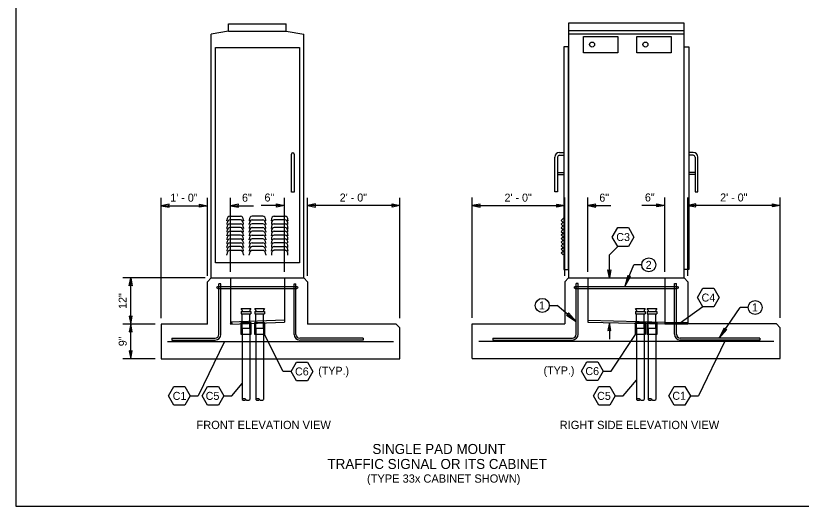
# Model space of a CAD drawing. Extents: x 99862 to 103151, y 100000 to 117076.
# Drawn here: x 99862 to 101432, y 109000 to 109981 of the extents above; entities that cross this region are included whole.
import ezdxf

# ---------------------------------------------------------------- set-up
doc = ezdxf.new("R2010")
doc.units = 0
for name, color, linetype in [('Default', 7, 'Continuous'), ('Level 1', 7, 'Continuous'), ('Level 11', 7, 'Continuous'), ('Level 15', 7, 'Continuous'), ('Level 20', 7, 'Continuous'), ('Level 40', 7, 'Continuous'), ('Level 6', 7, 'Continuous'), ('Level 60', 7, 'Continuous')]:
    doc.layers.add(name, color=color, linetype=linetype)

msp = doc.modelspace()

# ---------------------------------------------------------------- linework, layer by layer
at = {"layer": 'Default'}
for p, q in [((100266.2, 109439.1), (100424, 109439.1)), ((100266.2, 109435.2), (100424, 109435.2)), ((100268.2, 109343.5), (100268.2, 109444.9)), ((100272, 109444.9), (100268.2, 109444.9)), ((100272, 109343.5), (100272, 109444.9)), ((100418.2, 109343.5), (100418.2, 109444.9)), ((100418.2, 109444.9), (100422.1, 109444.9)), ((100422.1, 109343.5), (100422.1, 109444.9)), ((100980.4, 109439.3), (101184.3, 109439.3)), ((100980.4, 109435.4), (101184.3, 109435.4)), ((100982.3, 109343.7), (100982.3, 109445.1)), ((100986.2, 109445.1), (100982.3, 109445.1)), ((100986.2, 109343.7), (100986.2, 109445.1)), ((101178.5, 109343.7), (101178.5, 109445.1)), ((101178.5, 109445.1), (101182.4, 109445.1)), ((101182.4, 109343.7), (101182.4, 109445.1)), ((101159.3, 109367.1), (101205.5, 109367.1)), ((101159.3, 109364.3), (101205.5, 109364.3)), ((100173.9, 109335.9), (100173.9, 109332)), ((100173.9, 109335.9), (100260.5, 109335.9)), ((100173.9, 109332), (100260.5, 109332)), ((100556.2, 109335.9), (100429.8, 109335.9)), ((100556.2, 109332), (100429.8, 109332)), ((100556.2, 109335.9), (100556.2, 109332)), ((100815.4, 109336), (100815.4, 109332.2)), ((100815.4, 109336), (100974.6, 109336)), ((100815.4, 109332.2), (100974.6, 109332.2)), ((101349.3, 109336), (101190.1, 109336)), ((101349.3, 109332.2), (101190.1, 109332.2)), ((101349.3, 109336), (101349.3, 109332.2))]:
    msp.add_line(p, q, dxfattribs=at)
for centre, radius in [((100266.2, 109437.2), 1.92), ((100424, 109437.2), 1.92), ((100980.4, 109437.4), 1.92), ((101184.3, 109437.4), 1.92), ((100292.7, 109365.5), 1.44)]:
    msp.add_circle(centre, radius, dxfattribs=at)
for centre, radius, start, end in [((100260.5, 109343.5), 11.5, 270, 0), ((100260.5, 109343.5), 7.7, 270, 0), ((100429.8, 109343.5), 11.5, 180, 270), ((100429.8, 109343.5), 7.7, 180, 270), ((100974.6, 109343.7), 11.5, 270, 0), ((100974.6, 109343.7), 7.7, 270, 0), ((101190.1, 109343.7), 11.5, 180, 270), ((101190.1, 109343.7), 7.7, 180, 270)]:
    msp.add_arc(centre, radius, start, end, dxfattribs=at)
at = {"layer": 'Level 1'}
for p, q in [((100312.5, 109395.5), (100331.8, 109395.5)), ((100312.5, 109389.2), (100312.5, 109384.7)), ((100312.5, 109389.2), (100331.8, 109389.2)), ((100312.5, 109384.7), (100331.8, 109384.7)), ((100314.5, 109391), (100314.5, 109389.2)), ((100314.5, 109355.3), (100314.5, 109384.7)), ((100329.9, 109391), (100329.9, 109389.2)), ((100329.9, 109355.3), (100329.9, 109384.7)), ((100331.8, 109389.2), (100331.8, 109384.7)), ((100339.8, 109395.5), (100359, 109395.5)), ((100339.8, 109389.2), (100339.8, 109384.7)), ((100339.8, 109389.2), (100359, 109389.2)), ((100339.8, 109384.7), (100359, 109384.7)), ((100341.7, 109391), (100341.7, 109389.2)), ((100341.7, 109355.3), (100341.7, 109384.7)), ((100357.1, 109391), (100357.1, 109389.2)), ((100357.1, 109355.3), (100357.1, 109384.7)), ((100359, 109389.2), (100359, 109384.7)), ((101100.5, 109395.5), (101119.8, 109395.5)), ((101100.5, 109389.2), (101100.5, 109384.7)), ((101100.5, 109389.2), (101119.8, 109389.2)), ((101100.5, 109384.7), (101119.8, 109384.7)), ((101102.5, 109391), (101102.5, 109389.2)), ((101102.5, 109355.3), (101102.5, 109384.7)), ((101117.8, 109391), (101117.8, 109389.2)), ((101117.8, 109355.3), (101117.8, 109384.7)), ((101119.8, 109389.2), (101119.8, 109384.7)), ((101123.9, 109395.5), (101143.1, 109395.5)), ((101123.9, 109389.2), (101123.9, 109384.7)), ((101123.9, 109389.2), (101143.1, 109389.2)), ((101123.9, 109384.7), (101143.1, 109384.7)), ((101125.8, 109391), (101125.8, 109389.2)), ((101125.8, 109355.3), (101125.8, 109384.7)), ((101141.2, 109391), (101141.2, 109389.2)), ((101141.2, 109355.3), (101141.2, 109384.7)), ((101143.1, 109389.2), (101143.1, 109384.7)), ((100329.9, 109355.3), (100314.5, 109355.3)), ((100314.5, 109355.3), (100314.5, 109213.2)), ((100329.9, 109355.3), (100329.9, 109213.2)), ((100357.1, 109355.3), (100341.7, 109355.3)), ((100341.7, 109355.3), (100341.7, 109213.2)), ((100357.1, 109355.3), (100357.1, 109213.2)), ((101117.8, 109355.3), (101102.5, 109355.3)), ((101102.5, 109355.3), (101102.5, 109213.2)), ((101117.8, 109355.3), (101117.8, 109213.2)), ((101141.2, 109355.3), (101125.8, 109355.3)), ((101125.8, 109355.3), (101125.8, 109213.2)), ((101141.2, 109355.3), (101141.2, 109213.2))]:
    msp.add_line(p, q, dxfattribs=at)
for points in [[(99862, 108999.5), (103151, 108999.5), (103151, 111075.5), (99862, 111075.5)], [(100331.8, 109343.4), (100312.5, 109343.4), (100312.5, 109367.2), (100331.8, 109367.2)], [(100359, 109343.4), (100339.8, 109343.4), (100339.8, 109367.2), (100359, 109367.2)], [(101119.8, 109343.4), (101100.5, 109343.4), (101100.5, 109367.2), (101119.8, 109367.2)], [(101143.1, 109343.4), (101123.9, 109343.4), (101123.9, 109367.2), (101143.1, 109367.2)]]:
    msp.add_lwpolyline(points, close=True, dxfattribs=at)
for centre, radius, start, end in [((100308.2, 109391), 6.32, 0, 45.9402), ((100336.2, 109391), 6.32, 134.0598, 180), ((100335.4, 109391), 6.32, 0, 45.9402), ((100363.4, 109391), 6.32, 134.0598, 180), ((101096.1, 109391), 6.32, 0, 45.9402), ((101124.2, 109391), 6.32, 134.0598, 180), ((101119.5, 109391), 6.32, 0, 45.9402), ((101147.5, 109391), 6.32, 134.0598, 180), ((100318.3, 109208.5), 6.09, 50.8329, 129.1671), ((100318.3, 109217.9), 6.09, 230.8329, 309.1671), ((100326, 109217.9), 6.09, 230.8329, 309.1671), ((100345.5, 109208.5), 6.09, 50.8329, 129.1671), ((100345.5, 109217.9), 6.09, 230.8329, 309.1671), ((100353.2, 109217.9), 6.09, 230.8329, 309.1671), ((101106.3, 109208.5), 6.09, 50.8329, 129.1671), ((101106.3, 109217.9), 6.09, 230.8329, 309.1671), ((101114, 109217.9), 6.09, 230.8329, 309.1671), ((101129.6, 109208.5), 6.09, 50.8329, 129.1671), ((101129.6, 109217.9), 6.09, 230.8329, 309.1671), ((101137.3, 109217.9), 6.09, 230.8329, 309.1671)]:
    msp.add_arc(centre, radius, start, end, dxfattribs=at)
at = {"layer": 'Level 11'}
for p, q in [((100291.3, 109456.4), (100291.3, 109364.1)), ((100399, 109456.4), (100399, 109367.9)), ((101005.4, 109456.6), (101005.4, 109368.1)), ((101159.3, 109456.6), (101159.3, 109364.3)), ((100399, 109371.8), (100291.3, 109367.9)), ((101005.4, 109372), (101159.3, 109368.1)), ((100291.3, 109364.1), (100399, 109367.9)), ((100774.5, 109295), (100774.5, 109364.3)), ((101005.4, 109368.1), (101159.3, 109364.3))]:
    msp.add_line(p, q, dxfattribs=at)
for points in [[(100245.1, 109364.1), (100245.1, 109448.7), (100252.8, 109456.4)], [(100252.8, 109456.4), (100437.5, 109456.4)], [(100437.5, 109456.4), (100445.2, 109448.7), (100445.2, 109364.1)], [(100966.9, 109456.6), (100959.2, 109448.9), (100959.2, 109364.3)], [(100966.9, 109456.6), (101197.8, 109456.6)], [(101197.8, 109456.6), (101205.5, 109448.9), (101205.5, 109364.3)], [(100245.1, 109364.1), (100152.7, 109364.1)], [(100152.7, 109364.1), (100152.7, 109294.8)], [(100622.1, 109364.1), (100445.2, 109364.1)], [(100629.8, 109294.8), (100629.8, 109356.4), (100622.1, 109364.1)], [(100774.5, 109364.3), (100959.2, 109364.3)], [(101382.4, 109364.3), (101205.5, 109364.3)], [(101390.1, 109295), (101390.1, 109356.6), (101382.4, 109364.3)], [(100152.7, 109294.8), (100629.8, 109294.8)], [(100774.5, 109295), (101390.1, 109295)]]:
    msp.add_lwpolyline(points, dxfattribs=at)
at = {"layer": 'Level 15'}
for p, q in [((100152.7, 109376.1), (100152.7, 109616.9)), ((100245.1, 109460.7), (100245.1, 109616.9)), ((100291.3, 109468.4), (100291.3, 109616.9)), ((100399, 109468.4), (100399, 109616.9)), ((100445.2, 109460.7), (100445.2, 109616.9)), ((100629.8, 109376.1), (100629.8, 109616.9)), ((100774.5, 109376.3), (100774.5, 109617)), ((100959.2, 109460.9), (100959.2, 109617)), ((101005.4, 109468.6), (101005.4, 109617)), ((101159.3, 109468.6), (101159.3, 109617)), ((101205.5, 109460.9), (101205.5, 109617)), ((101390.1, 109376.3), (101390.1, 109617)), ((100152.7, 109600.9), (100245.1, 109600.9)), ((100291.3, 109600.9), (100337.4, 109600.9)), ((100399, 109601.2), (100352.8, 109601.2)), ((100629.8, 109601.2), (100445.2, 109601.2)), ((100774.5, 109601), (100959.2, 109601)), ((101005.4, 109601), (101051.6, 109601)), ((101159.3, 109601.4), (101113.1, 109601.4)), ((101390.1, 109601.4), (101205.5, 109601.4)), ((100245.1, 109460.7), (100245.1, 109526.2)), ((101048.4, 109502.8), (101065.2, 109519.5)), ((101048.4, 109456.6), (101048.4, 109502.8)), ((101079.1, 109439.3), (101097.2, 109482.5)), ((101113.2, 109482.5), (101097.2, 109482.5)), ((100240.8, 109456.4), (100075.8, 109456.4)), ((100091.8, 109364.1), (100091.8, 109456.4)), ((100928.4, 109401.4), (100944.4, 109401.4)), ((100982.3, 109369.3), (100944.4, 109401.4)), ((101235.5, 109398.4), (101189.9, 109365.9)), ((101268, 109336), (101309.9, 109397.3)), ((101325.9, 109397.3), (101309.9, 109397.3)), ((100140.7, 109364.1), (100075.8, 109364.1)), ((100091.8, 109294.8), (100091.8, 109364.1)), ((101048.4, 109367), (101048.4, 109333.7)), ((100396.5, 109269.2), (100359, 109343.4)), ((101052, 109270), (101100.5, 109343.4)), ((100279.6, 109329.4), (100226.6, 109220.4)), ((101279.2, 109329.6), (101226.3, 109220.6)), ((100140.7, 109294.8), (100075.8, 109294.8)), ((100412.5, 109269.2), (100396.5, 109269.2)), ((101036, 109270), (101052, 109270)), ((100293.9, 109220.4), (100314.5, 109245)), ((101076.2, 109220.4), (101102.5, 109251.7)), ((100210.6, 109220.4), (100226.6, 109220.4)), ((100277.9, 109220.4), (100293.9, 109220.4)), ((101060.2, 109220.4), (101076.2, 109220.4)), ((101210.3, 109220.6), (101226.3, 109220.6))]:
    msp.add_line(p, q, dxfattribs=at)
for points in [[(100399, 109601.2), (100383.3, 109598.2), (100384, 109601.2), (100383.3, 109604.3)], [(100445.2, 109601.2), (100460.9, 109598.2), (100460.2, 109601.2), (100460.9, 109604.3)], [(100629.8, 109601.2), (100614.1, 109598.2), (100614.8, 109601.2), (100614.1, 109604.3)], [(100774.5, 109601), (100790.3, 109598), (100789.5, 109601), (100790.3, 109604.1)], [(100959.2, 109601), (100943.5, 109598), (100944.2, 109601), (100943.5, 109604.1)], [(101005.4, 109601), (101021.1, 109598), (101020.4, 109601), (101021.1, 109604.1)], [(101159.3, 109601.4), (101143.6, 109598.3), (101144.3, 109601.4), (101143.6, 109604.5)], [(101205.5, 109601.4), (101221.2, 109598.3), (101220.5, 109601.4), (101221.2, 109604.5)], [(101390.1, 109601.4), (101374.4, 109598.3), (101375.1, 109601.4), (101374.4, 109604.5)], [(100152.7, 109600.9), (100168.5, 109597.8), (100167.7, 109600.9), (100168.5, 109603.9)], [(100245.1, 109600.9), (100229.4, 109597.8), (100230.1, 109600.9), (100229.4, 109603.9)], [(100291.3, 109600.9), (100307, 109597.8), (100306.3, 109600.9), (100307, 109603.9)], [(101048.4, 109456.6), (101045.3, 109472.3), (101048.4, 109471.6), (101051.5, 109472.3)], [(100091.8, 109456.4), (100094.9, 109440.7), (100091.8, 109441.4), (100088.7, 109440.7)], [(101079.1, 109439.3), (101090.7, 109459.2), (101087.5, 109459.4), (101085.2, 109461.5)], [(100982.3, 109369.3), (100966.8, 109386.3), (100965.7, 109383.4), (100963, 109381.8)], [(100091.8, 109364.1), (100094.9, 109379.8), (100091.8, 109379.1), (100088.7, 109379.8)], [(100091.8, 109364.1), (100088.7, 109348.3), (100091.8, 109349.1), (100094.9, 109348.3)], [(101048.4, 109367), (101045.3, 109351.3), (101048.4, 109352), (101051.5, 109351.3)], [(101268, 109336), (101278.4, 109356.6), (101280.3, 109354), (101283.4, 109353.2)], [(100091.8, 109294.8), (100094.9, 109310.5), (100091.8, 109309.8), (100088.7, 109310.5)]]:
    msp.add_lwpolyline(points, close=True, dxfattribs=at)
at = {"layer": 'Level 20'}
for points in [[(101054.3, 109538.2), (101065.2, 109557), (101086.8, 109557), (101097.6, 109538.2), (101086.8, 109519.5), (101065.2, 109519.5), (101054.3, 109538.2)], [(101224.7, 109417.1), (101235.5, 109435.9), (101257.2, 109435.9), (101268, 109417.1), (101257.2, 109398.4), (101235.5, 109398.4), (101224.7, 109417.1)], [(100412.5, 109269.2), (100423.3, 109288), (100445, 109288), (100455.8, 109269.2), (100445, 109250.5), (100423.3, 109250.5), (100412.5, 109269.2)], [(100992.7, 109270), (101003.5, 109288.7), (101025.2, 109288.7), (101036, 109270), (101025.2, 109251.2), (101003.5, 109251.2), (100992.7, 109270)], [(100167.4, 109220.4), (100178.2, 109239.2), (100199.8, 109239.2), (100210.6, 109220.4), (100199.8, 109201.7), (100178.2, 109201.7), (100167.4, 109220.4)], [(100234.6, 109220.4), (100245.4, 109239.2), (100267, 109239.2), (100277.9, 109220.4), (100267, 109201.7), (100245.4, 109201.7), (100234.6, 109220.4)], [(101016.9, 109220.4), (101027.7, 109239.2), (101049.3, 109239.2), (101060.2, 109220.4), (101049.3, 109201.7), (101027.7, 109201.7), (101016.9, 109220.4)], [(101167, 109220.6), (101177.8, 109239.4), (101199.5, 109239.4), (101210.3, 109220.6), (101199.5, 109201.9), (101177.8, 109201.9), (101167, 109220.6)]]:
    msp.add_lwpolyline(points, dxfattribs=at)
for centre in [(101127.2, 109482.5), (100914.4, 109401.4), (101339.9, 109397.3)]:
    msp.add_circle(centre, 14, dxfattribs=at)
at = {"layer": 'Level 40'}
for p, q in [((100165.6, 109329.4), (100617, 109329.4)), ((100787.4, 109329.6), (101377.3, 109329.6))]:
    msp.add_line(p, q, dxfattribs=at)
at = {"layer": 'Level 6'}
for p, q in [((101197.8, 109966.2), (100966.9, 109966.2)), ((100966.9, 109966.2), (100966.9, 109456.6)), ((101197.8, 109456.6), (101197.8, 109966.2)), ((100287.5, 109950.2), (100252.8, 109943.8)), ((100287.5, 109950.2), (100287.5, 109965)), ((100287.5, 109965), (100402.7, 109965)), ((100287.5, 109950.2), (100402.7, 109950.2)), ((100402.7, 109950.2), (100402.7, 109965)), ((100402.7, 109950.2), (100437.5, 109943.8)), ((100966.9, 109951.4), (101197.8, 109951.4)), ((100252.8, 109456.4), (100252.8, 109943.8)), ((100437.5, 109456.4), (100437.5, 109943.8)), ((100966.9, 109945), (101197.8, 109945)), ((100413, 109700.1), (100413, 109703.9)), ((100413, 109627.8), (100413, 109700.1)), ((100418.7, 109703.9), (100418.7, 109700.1)), ((100418.7, 109700.1), (100418.7, 109627.8)), ((100948.6, 109707.5), (100957.3, 109707.5)), ((100948.6, 109701.8), (100957.3, 109701.8)), ((101216.1, 109707.5), (101207.4, 109707.5)), ((101216.1, 109701.8), (101207.4, 109701.8)), ((100939.2, 109628.3), (100939.2, 109698.1)), ((100944.9, 109698.1), (100944.9, 109628.3)), ((101219.7, 109698.1), (101219.7, 109628.3)), ((101225.5, 109628.3), (101225.5, 109698.1)), ((100944.9, 109667), (100957.3, 109667)), ((101219.7, 109667), (101207.4, 109667)), ((100944.9, 109663.5), (100957.3, 109663.5)), ((101219.7, 109663.5), (101207.4, 109663.5)), ((100418.7, 109627.8), (100413, 109627.8)), ((100944.9, 109628.3), (100939.2, 109628.3)), ((101219.7, 109628.3), (101225.5, 109628.3)), ((100289.9, 109580.1), (100311.4, 109580.1)), ((100355.9, 109580.1), (100334.4, 109580.1)), ((100378.8, 109580.1), (100400.3, 109580.1)), ((100952.2, 109571.3), (100957.3, 109576.3)), ((100284.2, 109570.8), (100284.2, 109572.1)), ((100284.2, 109564.5), (100284.2, 109563.2)), ((100311.4, 109572.5), (100289.9, 109572.5)), ((100289.9, 109564.9), (100311.4, 109564.9)), ((100311.4, 109557.3), (100289.9, 109557.3)), ((100317.1, 109572.1), (100317.1, 109570.8)), ((100317.1, 109563.2), (100317.1, 109564.5)), ((100328.7, 109572.1), (100328.7, 109570.8)), ((100328.7, 109563.2), (100328.7, 109564.5)), ((100334.4, 109572.5), (100355.9, 109572.5)), ((100355.9, 109564.9), (100334.4, 109564.9)), ((100334.4, 109557.3), (100355.9, 109557.3)), ((100361.6, 109570.8), (100361.6, 109572.1)), ((100361.6, 109564.5), (100361.6, 109563.2)), ((100373.1, 109570.8), (100373.1, 109572.1)), ((100373.1, 109564.5), (100373.1, 109563.2)), ((100400.3, 109572.5), (100378.8, 109572.5)), ((100378.8, 109564.9), (100400.3, 109564.9)), ((100400.3, 109557.3), (100378.8, 109557.3)), ((100406, 109572.1), (100406, 109570.8)), ((100406, 109563.2), (100406, 109564.5)), ((100952.2, 109571.3), (100956, 109567.4)), ((100952.2, 109564.1), (100955.8, 109567.7)), ((100952.2, 109564.1), (100956, 109560.2)), ((100952.2, 109556.8), (100955.8, 109560.5)), ((100284.2, 109555.5), (100284.2, 109556.8)), ((100284.2, 109549.2), (100284.2, 109547.9)), ((100284.2, 109540.3), (100284.2, 109541.6)), ((100289.9, 109549.7), (100311.4, 109549.7)), ((100311.4, 109542.1), (100289.9, 109542.1)), ((100317.1, 109556.8), (100317.1, 109555.5)), ((100317.1, 109547.9), (100317.1, 109549.2)), ((100317.1, 109541.6), (100317.1, 109540.3)), ((100328.7, 109556.8), (100328.7, 109555.5)), ((100328.7, 109547.9), (100328.7, 109549.2)), ((100328.7, 109541.6), (100328.7, 109540.3)), ((100355.9, 109549.7), (100334.4, 109549.7)), ((100334.4, 109542.1), (100355.9, 109542.1)), ((100361.6, 109555.5), (100361.6, 109556.8)), ((100361.6, 109549.2), (100361.6, 109547.9)), ((100361.6, 109540.3), (100361.6, 109541.6)), ((100373.1, 109555.5), (100373.1, 109556.8)), ((100373.1, 109549.2), (100373.1, 109547.9)), ((100373.1, 109540.3), (100373.1, 109541.6)), ((100378.8, 109549.7), (100400.3, 109549.7)), ((100400.3, 109542.1), (100378.8, 109542.1)), ((100406, 109556.8), (100406, 109555.5)), ((100406, 109547.9), (100406, 109549.2)), ((100406, 109541.6), (100406, 109540.3)), ((100952.2, 109556.8), (100956, 109553)), ((100952.2, 109549.6), (100955.8, 109553.2)), ((100952.2, 109549.6), (100956, 109545.8)), ((100952.2, 109542.4), (100955.8, 109546)), ((100952.2, 109542.4), (100956, 109538.6)), ((100284.2, 109534), (100284.2, 109532.7)), ((100284.2, 109525.1), (100284.2, 109526.4)), ((100289.9, 109534.5), (100311.4, 109534.5)), ((100289.9, 109526.8), (100311.4, 109526.8)), ((100317.1, 109532.7), (100317.1, 109534)), ((100317.1, 109526.4), (100317.1, 109525.1)), ((100328.7, 109532.7), (100328.7, 109534)), ((100328.7, 109526.4), (100328.7, 109525.1)), ((100355.9, 109534.5), (100334.4, 109534.5)), ((100334.4, 109526.8), (100355.9, 109526.8)), ((100361.6, 109534), (100361.6, 109532.7)), ((100361.6, 109525.1), (100361.6, 109526.4)), ((100373.1, 109534), (100373.1, 109532.7)), ((100373.1, 109525.1), (100373.1, 109526.4)), ((100378.8, 109534.5), (100400.3, 109534.5)), ((100400.3, 109526.8), (100378.8, 109526.8)), ((100406, 109532.7), (100406, 109534)), ((100952.2, 109535.2), (100955.8, 109538.8)), ((100952.2, 109535.2), (100956, 109531.4)), ((100952.2, 109528), (100955.8, 109531.6)), ((100952.2, 109528), (100956, 109524.2)), ((100284.2, 109517.5), (100284.2, 109518.8)), ((100284.2, 109511.1), (100284.2, 109509.8)), ((100311.4, 109519.2), (100289.9, 109519.2)), ((100289.9, 109511.6), (100311.4, 109511.6)), ((100317.1, 109518.8), (100317.1, 109517.5)), ((100317.1, 109509.8), (100317.1, 109511.1)), ((100328.7, 109517.5), (100328.7, 109518.8)), ((100328.7, 109511.1), (100328.7, 109509.8)), ((100355.9, 109519.2), (100334.4, 109519.2)), ((100334.4, 109511.6), (100355.9, 109511.6)), ((100361.6, 109518.8), (100361.6, 109517.5)), ((100361.6, 109509.8), (100361.6, 109511.1)), ((100373.1, 109518.8), (100373.1, 109517.5)), ((100373.1, 109509.8), (100373.1, 109511.1)), ((100378.8, 109519.2), (100400.3, 109519.2)), ((100400.3, 109511.6), (100378.8, 109511.6)), ((100406, 109517.5), (100406, 109518.8)), ((100406, 109511.1), (100406, 109509.8)), ((100952.2, 109520.8), (100955.8, 109524.4)), ((100952.2, 109520.8), (100956, 109516.9)), ((100952.2, 109513.6), (100955.8, 109517.2)), ((100952.2, 109513.6), (100956, 109509.7)), ((100952.2, 109506.3), (100955.8, 109510)), ((100284.2, 109502.2), (100284.2, 109503.5)), ((100317.1, 109503.5), (100317.1, 109502.2)), ((100328.7, 109502.2), (100328.7, 109503.5)), ((100361.6, 109503.5), (100361.6, 109502.2)), ((100373.1, 109503.5), (100373.1, 109502.2)), ((100406, 109502.2), (100406, 109503.5)), ((100952.2, 109506.3), (100956, 109502.5)), ((100252.8, 109456.4), (100437.5, 109456.4)), ((100966.9, 109456.6), (101197.8, 109456.6))]:
    msp.add_line(p, q, dxfattribs=at)
for points in [[(100997, 109939.7), (101065.1, 109939.7), (101065.1, 109907), (100997, 109907)], [(101103.5, 109939.7), (101171.7, 109939.7), (101171.7, 109907), (101103.5, 109907)], [(100966.9, 109918.7), (100957.3, 109918.7), (100957.3, 109473.4), (100966.9, 109473.4)], [(101197.8, 109918.7), (101207.4, 109918.7), (101207.4, 109473.4), (101197.8, 109473.4)], [(100261.4, 109917.2), (100428.9, 109917.2), (100428.9, 109486.9), (100261.4, 109486.9)]]:
    msp.add_lwpolyline(points, close=True, dxfattribs=at)
for centre in [(101013.9, 109923.3), (101120.4, 109923.3)]:
    msp.add_circle(centre, 5.05, dxfattribs=at)
for centre, radius, start, end in [((100415.8, 109703.9), 2.86, 0, 180), ((100948.6, 109698.1), 9.36, 90, 180), ((100948.6, 109698.1), 3.64, 90, 180), ((101216.1, 109698.1), 9.36, 0, 90), ((101216.1, 109698.1), 3.64, 0, 90)]:
    msp.add_arc(centre, radius, start, end, dxfattribs=at)
for centre, start_param, end_param in [((100289.9, 109572.1), 0, 1.570796), ((100311.4, 109572.1), 4.712389, 6.283185), ((100334.4, 109572.1), 0, 1.570796), ((100355.9, 109572.1), 4.712389, 6.283185), ((100378.8, 109572.1), 0, 1.570796), ((100400.3, 109572.1), 4.712389, 6.283185), ((100289.9, 109564.5), 0, 1.570796), ((100289.9, 109556.8), 0, 1.570796), ((100289.9, 109549.2), 0, 1.570796), ((100311.4, 109564.5), 4.712389, 6.283185), ((100311.4, 109556.8), 4.712389, 6.283185), ((100311.4, 109549.2), 4.712389, 6.283185), ((100334.4, 109564.5), 0, 1.570796), ((100334.4, 109556.8), 0, 1.570796), ((100334.4, 109549.2), 0, 1.570796), ((100355.9, 109564.5), 4.712389, 6.283185), ((100355.9, 109556.8), 4.712389, 6.283185), ((100355.9, 109549.2), 4.712389, 6.283185), ((100378.8, 109564.5), 0, 1.570796), ((100378.8, 109556.8), 0, 1.570796), ((100378.8, 109549.2), 0, 1.570796), ((100400.3, 109564.5), 4.712389, 6.283185), ((100400.3, 109556.8), 4.712389, 6.283185), ((100400.3, 109549.2), 4.712389, 6.283185), ((100289.9, 109541.6), 0, 1.570796), ((100289.9, 109534), 0, 1.570796), ((100311.4, 109541.6), 4.712389, 6.283185), ((100311.4, 109534), 4.712389, 6.283185), ((100334.4, 109541.6), 0, 1.570796), ((100334.4, 109534), 0, 1.570796), ((100355.9, 109541.6), 4.712389, 6.283185), ((100355.9, 109534), 4.712389, 6.283185), ((100378.8, 109541.6), 0, 1.570796), ((100378.8, 109534), 0, 1.570796), ((100400.3, 109541.6), 4.712389, 6.283185), ((100400.3, 109534), 4.712389, 6.283185), ((100289.9, 109526.4), 0, 1.570796), ((100289.9, 109518.8), 0, 1.570796), ((100311.4, 109526.4), 4.712389, 6.283185), ((100311.4, 109518.8), 4.712389, 6.283185), ((100334.4, 109526.4), 0, 1.570796), ((100334.4, 109518.8), 0, 1.570796), ((100355.9, 109526.4), 4.712389, 6.283185), ((100355.9, 109518.8), 4.712389, 6.283185), ((100378.8, 109526.4), 0, 1.570796), ((100378.8, 109518.8), 0, 1.570796), ((100400.3, 109526.4), 4.712389, 6.283185), ((100400.3, 109518.8), 4.712389, 6.283185), ((100289.9, 109511.1), 0, 1.570796), ((100289.9, 109503.5), 0, 1.570796), ((100311.4, 109511.1), 4.712389, 6.283185), ((100311.4, 109503.5), 4.712389, 6.283185), ((100334.4, 109511.1), 0, 1.570796), ((100334.4, 109503.5), 0, 1.570796), ((100355.9, 109511.1), 4.712389, 6.283185), ((100355.9, 109503.5), 4.712389, 6.283185), ((100378.8, 109511.1), 0, 1.570796), ((100378.8, 109503.5), 0, 1.570796), ((100400.3, 109511.1), 4.712389, 6.283185), ((100400.3, 109503.5), 4.712389, 6.283185)]:
    msp.add_ellipse(centre, major_axis=(0, 8.08), ratio=0.707107, start_param=start_param, end_param=end_param, dxfattribs=at)
at = {"layer": 'Level 60'}
msp.add_line((99862, 108999.5), (99862, 108999.5), dxfattribs=at)

# ---------------------------------------------------------------- texts
at = {"layer": 'Level 20'}
for s, height, p in [('1\' - 0"', 16, (100171, 109608.9)), ('6"', 16, (100314.3, 109608.9)), ('6"', 16, (100359.2, 109609.2)), ('2\' - 0"', 16, (100509.6, 109609.2)), ('2\' - 0"', 16, (100838.9, 109609)), ('6"', 16, (101028.4, 109609)), ('6"', 16, (101119.5, 109609.4)), ('2\' - 0"', 16, (101269.9, 109609.4)), ('C3', 16, (101062.3, 109530.2)), ('2', 16, (101121.1, 109474.5)), ('C4', 16, (101232.7, 109409.1)), ('1', 16, (100907.8, 109393.4)), ('1', 16, (101333.3, 109389.3)), ('C6', 16, (100420.2, 109261.3)), ('(TYP.)', 16, (100466.5, 109262.6)), ('(TYP.)', 16, (100916.9, 109263.3)), ('C6', 16, (101000.5, 109262)), ('C1', 16, (100175.8, 109212.4)), ('C5', 16, (100241.7, 109212.4)), ('C5', 16, (101024, 109212.4)), ('C1', 16, (101174.3, 109212.6)), ('FRONT ELEVATION VIEW', 16.5, (100223.3, 109154)), ('RIGHT SIDE ELEVATION VIEW', 16.5, (100949.2, 109154)), ('SINGLE PAD MOUNT', 20, (100574.9, 109104.2)), ('TRAFFIC SIGNAL OR ITS CABINET', 20, (100485.1, 109074.2)), ('(TYPE 33x CABINET SHOWN)', 16.5, (100564.1, 109046.8))]:
    msp.add_text(s, height=height, dxfattribs=at).set_placement(p)
for s, p in [('12"', (100083.8, 109394.4)), ('9"', (100083.8, 109319.8))]:
    msp.add_text(s, height=16, rotation=90, dxfattribs=at).set_placement(p)

doc.saveas('drawing.dxf')
